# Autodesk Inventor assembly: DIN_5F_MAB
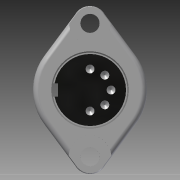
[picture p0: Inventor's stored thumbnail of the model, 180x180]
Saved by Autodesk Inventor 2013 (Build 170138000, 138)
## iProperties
Created: 2013-12
Part Number: DIN_5F_MAB
Document SubType Name: Assembly
Designer: leininger-65460
Author: leininger-65460
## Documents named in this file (3)
- C:\Documents and Settings\leininger-65460\My Documents\Stephane\Exercices Pratique Professionnelle\Amplificateur - Rack Son\Ampliambio\Mécanique\DIN_5F_MAB.iam
- C:\Documents and Settings\leininger-65460\My Documents\Stephane\Exercices Pratique Professionnelle\Amplificateur - Rack Son\Ampliambio\Mécanique\DIN_5F_MAB.ipt
- C:\Documents and Settings\leininger-65460\My Documents\Stephane\Exercices Pratique Professionnelle\Amplificateur - Rack Son\Ampliambio\Mécanique\Broche.ipt
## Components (6 placed, 2 different names)
1. DIN_5F_MAB:1 — Affleurement:1
2. Broche:1 — Affleurement:1, Affleurement:2
3. Broche:2
4. Broche:3
5. Broche:4
6. Broche:5
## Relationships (2: Flush 2)
- Affleurement:1 [Flush]: DIN_5F_MAB:1 ↔ Broche:1
- Affleurement:2 [Flush]: Broche:1
